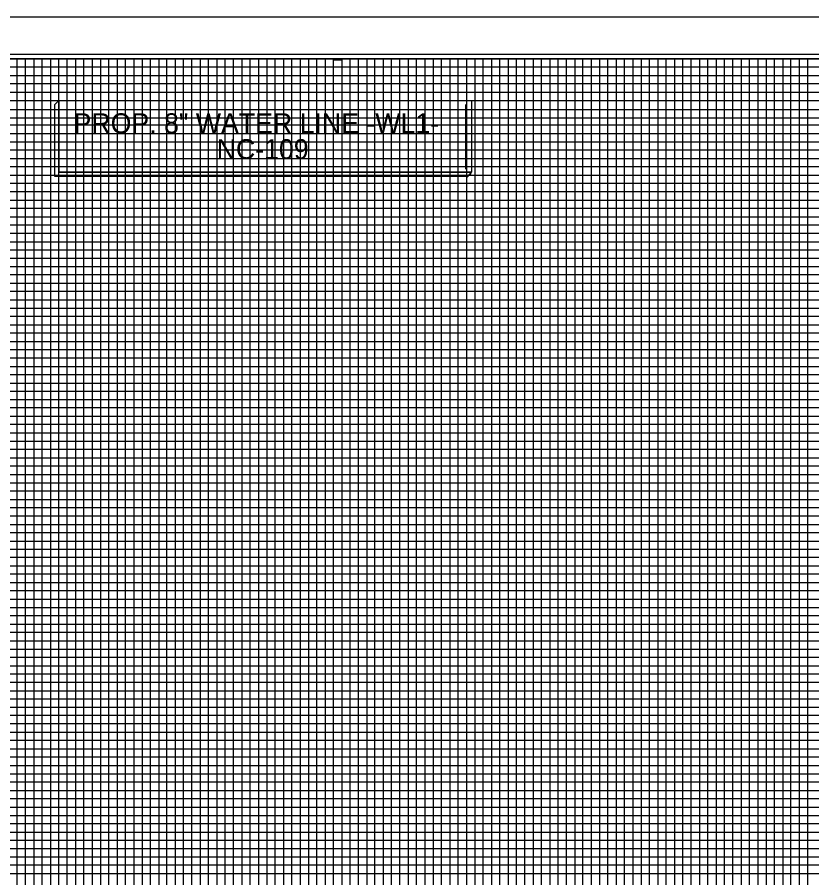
# Model space of a CAD drawing. Extents: x 3814791 to 3815465, y 1224203 to 1224643.
# Drawn here: x 3815088.1 to 3815279.1, y 1224436.2 to 1224643.2 of the extents above; entities that cross this region are included whole.
import ezdxf

# ---------------------------------------------------------------- set-up
doc = ezdxf.new("R2010")
doc.units = 0
for name, color, linetype in [('COGO Default Chain', 7, 'Continuous'), ('Exist Roads EOP', 7, 'Continuous'), ('Pattern 49', 7, 'Continuous'), ('Scratch_Level_1', 7, 'Continuous')]:
    doc.layers.add(name, color=color, linetype=linetype)

msp = doc.modelspace()

# ---------------------------------------------------------------- linework, layer by layer
at = {"layer": 'COGO Default Chain'}
for p, q in [((3815097.11, 1224622.19), (3815098.11, 1224623.19)), ((3815197.29, 1224605.91), (3815196.29, 1224604.91)), ((3815197.29, 1224605.91), (3815196.29, 1224604.91)), ((3815197.21, 1224605.62), (3815196.21, 1224604.62))]:
    msp.add_line(p, q, dxfattribs=at)
msp.add_lwpolyline([(3815098.11, 1224623.19), (3815197.29, 1224623.19), (3815197.29, 1224605.91), (3815098.11, 1224605.91)], close=True, dxfattribs=at)
for points in [[(3815098.11, 1224623.19), (3815098.11, 1224605.91), (3815197.29, 1224605.91)], [(3815196.29, 1224604.91), (3815097.11, 1224604.91), (3815097.11, 1224622.19)]]:
    msp.add_lwpolyline(points, dxfattribs=at)
at = {"layer": 'Exist Roads EOP'}
for p, q in [((3814878.11, 1224633.21), (3815378.11, 1224633.21)), ((3815195.89, 1224622.19), (3815195.89, 1224606.62)), ((3815438.11, 1224561.21), (3814878.11, 1224561.21)), ((3814878.11, 1224559.21), (3815438.11, 1224559.21)), ((3815438.11, 1224551.21), (3814878.11, 1224551.21))]:
    msp.add_line(p, q, dxfattribs=at)
for points in [[(3815458.11, 1224633.21), (3814858.11, 1224633.21), (3814858.11, 1224213.21), (3815458.11, 1224213.21)], [(3814878.11, 1224633.21), (3814878.11, 1224223.21), (3815438.11, 1224223.21), (3815438.11, 1224578.19), (3815378.11, 1224578.19), (3815378.11, 1224633.21)]]:
    msp.add_lwpolyline(points, close=True, dxfattribs=at)
for points in [[(3815088.11, 1224223.21), (3815088.11, 1224633.21), (3815108.11, 1224633.21), (3815108.11, 1224223.21)], [(3815090.11, 1224223.21), (3815090.11, 1224633.21), (3815092.11, 1224633.21), (3815092.11, 1224223.21)], [(3815094.11, 1224223.21), (3815094.11, 1224633.21), (3815096.11, 1224633.21), (3815096.11, 1224223.21)], [(3815098.11, 1224223.21), (3815098.11, 1224633.21), (3815118.11, 1224633.21), (3815118.11, 1224223.21)], [(3815100.11, 1224223.21), (3815100.11, 1224633.21), (3815102.11, 1224633.21), (3815102.11, 1224223.21)], [(3815104.11, 1224223.21), (3815104.11, 1224633.21), (3815106.11, 1224633.21), (3815106.11, 1224223.21)], [(3815110.11, 1224223.21), (3815110.11, 1224633.21), (3815112.11, 1224633.21), (3815112.11, 1224223.21)], [(3815114.11, 1224223.21), (3815114.11, 1224633.21), (3815116.11, 1224633.21), (3815116.11, 1224223.21)], [(3815120.11, 1224223.21), (3815120.11, 1224633.21), (3815122.11, 1224633.21), (3815122.11, 1224223.21)], [(3815124.11, 1224223.21), (3815124.11, 1224633.21), (3815126.11, 1224633.21), (3815126.11, 1224223.21)], [(3815128.11, 1224223.21), (3815128.11, 1224633.21), (3815148.11, 1224633.21), (3815148.11, 1224223.21)], [(3815130.11, 1224223.21), (3815130.11, 1224633.21), (3815132.11, 1224633.21), (3815132.11, 1224223.21)], [(3815134.11, 1224223.21), (3815134.11, 1224633.21), (3815136.11, 1224633.21), (3815136.11, 1224223.21)], [(3815138.11, 1224223.21), (3815138.11, 1224633.21), (3815158.11, 1224633.21), (3815158.11, 1224223.21)], [(3815140.11, 1224223.21), (3815140.11, 1224633.21), (3815142.11, 1224633.21), (3815142.11, 1224223.21)], [(3815144.11, 1224223.21), (3815144.11, 1224633.21), (3815146.11, 1224633.21), (3815146.11, 1224223.21)], [(3815150.11, 1224223.21), (3815150.11, 1224633.21), (3815152.11, 1224633.21), (3815152.11, 1224223.21)], [(3815154.11, 1224223.21), (3815154.11, 1224633.21), (3815156.11, 1224633.21), (3815156.11, 1224223.21)], [(3815160.11, 1224223.21), (3815160.11, 1224633.21), (3815162.11, 1224633.21), (3815162.11, 1224223.21)], [(3815164.11, 1224223.21), (3815164.11, 1224632.97), (3815166.11, 1224632.97), (3815166.11, 1224223.21)], [(3815168.11, 1224223.21), (3815168.11, 1224633.21), (3815188.11, 1224633.21), (3815188.11, 1224223.21)], [(3815170.11, 1224223.21), (3815170.11, 1224633.21), (3815172.11, 1224633.21), (3815172.11, 1224223.21)], [(3815174.11, 1224223.21), (3815174.11, 1224633.21), (3815176.11, 1224633.21), (3815176.11, 1224223.21)], [(3815178.11, 1224223.21), (3815178.11, 1224633.21), (3815198.11, 1224633.21), (3815198.11, 1224223.21)], [(3815180.11, 1224223.21), (3815180.11, 1224633.21), (3815182.11, 1224633.21), (3815182.11, 1224223.21)], [(3815184.11, 1224223.21), (3815184.11, 1224633.21), (3815186.11, 1224633.21), (3815186.11, 1224223.21)], [(3815190.11, 1224223.21), (3815190.11, 1224633.21), (3815192.11, 1224633.21), (3815192.11, 1224223.21)], [(3815194.11, 1224223.21), (3815194.11, 1224633.21), (3815196.11, 1224633.21), (3815196.11, 1224223.21)], [(3815200.11, 1224223.21), (3815200.11, 1224633.21), (3815202.11, 1224633.21), (3815202.11, 1224223.21)], [(3815204.11, 1224223.21), (3815204.11, 1224633.21), (3815206.11, 1224633.21), (3815206.11, 1224223.21)], [(3815208.11, 1224223.21), (3815208.11, 1224633.21), (3815228.11, 1224633.21), (3815228.11, 1224223.21)], [(3815210.11, 1224223.21), (3815210.11, 1224633.21), (3815212.11, 1224633.21), (3815212.11, 1224223.21)], [(3815214.11, 1224223.21), (3815214.11, 1224633.21), (3815216.11, 1224633.21), (3815216.11, 1224223.21)], [(3815218.11, 1224223.21), (3815218.11, 1224633.21), (3815238.11, 1224633.21), (3815238.11, 1224223.21)], [(3815220.11, 1224223.21), (3815220.11, 1224633.21), (3815222.11, 1224633.21), (3815222.11, 1224223.21)], [(3815224.11, 1224223.21), (3815224.11, 1224633.21), (3815226.11, 1224633.21), (3815226.11, 1224223.21)], [(3815230.11, 1224223.21), (3815230.11, 1224633.21), (3815232.11, 1224633.21), (3815232.11, 1224223.21)], [(3815234.11, 1224223.21), (3815234.11, 1224633.21), (3815236.11, 1224633.21), (3815236.11, 1224223.21)], [(3815240.11, 1224223.21), (3815240.11, 1224633.21), (3815242.11, 1224633.21), (3815242.11, 1224223.21)], [(3815244.11, 1224223.21), (3815244.11, 1224633.21), (3815246.11, 1224633.21), (3815246.11, 1224223.21)], [(3815248.11, 1224223.21), (3815248.11, 1224633.21), (3815268.11, 1224633.21), (3815268.11, 1224223.21)], [(3815250.11, 1224223.21), (3815250.11, 1224633.21), (3815252.11, 1224633.21), (3815252.11, 1224223.21)], [(3815254.11, 1224223.21), (3815254.11, 1224633.21), (3815256.11, 1224633.21), (3815256.11, 1224223.21)], [(3815258.11, 1224223.21), (3815258.11, 1224633.21), (3815278.11, 1224633.21), (3815278.11, 1224223.21)], [(3815260.11, 1224223.21), (3815260.11, 1224633.21), (3815262.11, 1224633.21), (3815262.11, 1224223.21)], [(3815264.11, 1224223.21), (3815264.11, 1224633.21), (3815266.11, 1224633.21), (3815266.11, 1224223.21)], [(3815270.11, 1224223.21), (3815270.11, 1224633.21), (3815272.11, 1224633.21), (3815272.11, 1224223.21)], [(3815274.11, 1224223.21), (3815274.11, 1224633.21), (3815276.11, 1224633.21), (3815276.11, 1224223.21)], [(3815378.09, 1224631.21), (3814878.11, 1224631.21), (3814878.11, 1224629.21), (3815378.09, 1224629.21)], [(3815378.09, 1224627.21), (3814878.11, 1224627.21), (3814878.11, 1224625.21), (3815378.09, 1224625.21)], [(3815378.09, 1224603.21), (3814858.15, 1224603.21), (3814858.15, 1224623.19), (3815378.09, 1224623.19)], [(3815378.09, 1224620.91), (3814878.11, 1224620.91)], [(3815378.09, 1224618.91), (3814878.11, 1224618.91)], [(3815378.09, 1224617.21), (3814878.11, 1224617.21), (3814878.11, 1224615.21), (3815378.09, 1224615.21)], [(3814858.11, 1224613.21), (3815378.09, 1224613.21)], [(3815378.09, 1224611.21), (3814878.11, 1224611.21), (3814878.11, 1224609.21), (3815378.09, 1224609.21)], [(3815378.11, 1224607.21), (3814878.11, 1224607.21), (3814878.11, 1224605.21), (3815378.09, 1224605.21)], [(3815378.09, 1224601.21), (3814878.11, 1224601.21), (3814878.11, 1224599.21), (3815378.09, 1224599.21)], [(3815378.09, 1224597.21), (3814878.11, 1224597.21), (3814878.11, 1224595.21), (3815378.09, 1224595.21)], [(3815378.09, 1224593.21), (3814858.11, 1224593.21), (3814858.11, 1224573.19), (3815458.11, 1224573.19)], [(3815378.09, 1224591.21), (3814878.11, 1224591.21), (3814878.11, 1224589.21), (3815378.09, 1224589.21)], [(3815378.09, 1224587.21), (3814878.11, 1224587.21), (3814878.11, 1224585.21), (3815378.09, 1224585.21)], [(3815458.11, 1224563.21), (3814858.11, 1224563.21), (3814858.11, 1224583.21), (3815378.09, 1224583.21)], [(3815378.09, 1224581.21), (3814878.11, 1224581.21), (3814878.11, 1224579.21), (3815378.09, 1224579.21)], [(3815438.11, 1224577.21), (3814878.11, 1224577.21), (3814878.11, 1224577.21), (3814878.11, 1224569.21), (3815438.11, 1224569.21)], [(3814878.11, 1224575.21), (3815438.11, 1224575.21)], [(3815438.11, 1224571.21), (3814878.11, 1224571.21)], [(3815438.11, 1224567.21), (3814878.11, 1224567.21), (3814878.11, 1224565.21), (3815438.11, 1224565.21)], [(3815438.11, 1224557.21), (3814878.11, 1224557.21), (3814878.11, 1224555.21), (3815438.11, 1224555.21)], [(3815458.11, 1224553.21), (3814858.11, 1224553.21), (3814858.11, 1224533.21), (3815458.11, 1224533.21)], [(3815438.11, 1224549.21), (3814878.11, 1224549.21), (3814878.11, 1224547.21), (3815438.11, 1224547.21)], [(3815438.11, 1224545.21), (3814878.11, 1224545.21)], [(3815458.11, 1224523.21), (3814858.11, 1224523.21), (3814858.11, 1224543.21), (3815458.11, 1224543.21)], [(3814878.11, 1224541.21), (3815438.11, 1224541.21)], [(3815438.11, 1224539.21), (3814878.11, 1224539.21), (3814878.11, 1224537.21), (3815438.11, 1224537.21)], [(3815438.11, 1224535.21), (3814878.11, 1224535.21), (3814878.11, 1224531.21), (3815438.11, 1224531.21)], [(3815438.11, 1224529.21), (3814878.11, 1224529.21), (3814878.11, 1224527.21), (3815438.11, 1224527.21)], [(3815438.11, 1224525.21), (3814878.11, 1224525.21), (3814878.11, 1224521.21), (3815438.11, 1224521.21)], [(3815438.11, 1224519.21), (3814878.11, 1224519.21), (3814878.11, 1224517.21), (3815438.11, 1224517.21)], [(3815438.11, 1224515.21), (3814878.11, 1224515.21), (3814878.11, 1224511.21), (3815438.11, 1224511.21)], [(3815458.11, 1224513.21), (3814858.11, 1224513.21), (3814858.11, 1224493.21), (3815458.11, 1224493.21)], [(3815438.11, 1224509.21), (3814878.11, 1224509.21), (3814878.11, 1224507.21), (3815438.11, 1224507.21)], [(3815438.11, 1224505.21), (3814878.11, 1224505.21), (3814878.11, 1224501.21), (3815438.11, 1224501.21)], [(3815458.11, 1224483.21), (3814858.11, 1224483.21), (3814858.11, 1224503.21), (3815458.11, 1224503.21)], [(3815438.11, 1224499.21), (3814878.11, 1224499.21), (3814878.11, 1224497.21), (3815438.11, 1224497.21)], [(3815438.11, 1224495.21), (3814878.11, 1224495.21), (3814878.11, 1224491.21), (3815438.11, 1224491.21)], [(3815438.11, 1224489.21), (3814878.11, 1224489.21), (3814878.11, 1224487.21), (3815438.11, 1224487.21)], [(3815438.11, 1224485.21), (3814878.11, 1224485.21), (3814878.11, 1224481.21), (3815438.11, 1224481.21)], [(3815438.11, 1224479.21), (3814878.11, 1224479.21), (3814878.11, 1224477.21), (3815438.11, 1224477.21)], [(3815438.11, 1224475.21), (3814878.11, 1224475.21), (3814878.11, 1224471.21), (3815438.11, 1224471.21)], [(3815458.11, 1224473.21), (3814858.11, 1224473.21), (3814858.11, 1224453.21), (3815458.11, 1224453.21)], [(3815438.11, 1224469.21), (3814878.11, 1224469.21), (3814878.11, 1224467.21), (3815438.11, 1224467.21)], [(3815438.11, 1224465.21), (3814878.11, 1224465.21), (3814878.11, 1224461.21), (3815438.11, 1224461.21)], [(3815458.11, 1224443.21), (3814858.11, 1224443.21), (3814858.11, 1224463.21), (3815458.11, 1224463.21)], [(3815438.11, 1224459.21), (3814878.11, 1224459.21), (3814878.11, 1224457.21), (3815438.11, 1224457.21)], [(3815438.11, 1224455.21), (3814878.11, 1224455.21), (3814878.11, 1224451.21), (3815438.11, 1224451.21)], [(3815438.11, 1224449.21), (3814878.11, 1224449.21), (3814878.11, 1224447.21), (3815438.11, 1224447.21)], [(3815438.11, 1224445.21), (3814878.11, 1224445.21), (3814878.11, 1224441.21), (3815438.11, 1224441.21)], [(3815438.11, 1224439.21), (3814878.11, 1224439.21), (3814878.11, 1224437.21), (3815438.11, 1224437.21)]]:
    msp.add_lwpolyline(points, dxfattribs=at)
at = {"layer": 'Pattern 49'}
msp.add_lwpolyline([(3815463.11, 1224634.23), (3814796.51, 1224634.23), (3814796.51, 1224212.19), (3815463.11, 1224212.19)], close=True, dxfattribs=at)
at = {"layer": 'Scratch_Level_1'}
msp.add_lwpolyline([(3815464.91, 1224643.21), (3814791.31, 1224643.21), (3814791.31, 1224203.21), (3815464.91, 1224203.21)], close=True, dxfattribs=at)

# ---------------------------------------------------------------- texts
at = {"layer": 'COGO Default Chain'}
for s, p in [('PROP. 8" WATER LINE -WL1-', (3815101.65, 1224615.29)), ('NC-109', (3815136.05, 1224609.07))]:
    msp.add_text(s, height=4.8, rotation=360, dxfattribs=at).set_placement(p)

doc.saveas('drawing.dxf')
